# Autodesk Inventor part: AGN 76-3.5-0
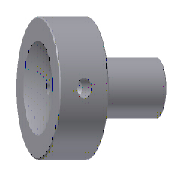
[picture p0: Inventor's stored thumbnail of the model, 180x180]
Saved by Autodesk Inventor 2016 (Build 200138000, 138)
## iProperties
IsCustomPart: 1
Created: 2015-02
Part Number: AGN 76-3.5-0
Material: DIN 1.2312
Description: Sprue Bushing
Document SubType Name: Modeling
Designer: Sandeep
Standard Revision: 1
Manufacturer: DME
Language: en-US
Size Designation: 76-3.5-0
Categories: <MemberInstance><Categories><Category DisplayName="Mold" InternalName="349578f2-f4d4-4954-8c09-8e99297a61c0" Mnemonic="MOLD"><Category DisplayName="Runners" Int
Density: 7.85 g/cm^3
Appearance: Default
Author: Sandeep
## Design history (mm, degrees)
sketch "Sketch1"
  geometry: L1 (0, -27.2)-(0, 23.2) reference; L2 (1.75, 20)-(19, 20); L3 (19, 20)-(19, 0); L4 (19, 0)-(12, 0); L5 (9, -3)-(9, -76); L6 (9, -76)-(4.264, -76); L7 (4.264, -76)-(1.75, 20); A1 r 3 centre (12, -3) between (12, 0) and (9, -3); 2 further points
  constraints: 12 end point, 3 parallel, 2 perpendicular, 2 point on circle, 2 point on line, 2 tangent, 1 centre point
  dimensions: "d0" = 18 diameter of L5 L1 (= D); "d3" = 38 diameter of L3 L1 (= d1); "d6" = 1.5 deg angle of L7 L1 (= 0.5 x Taper); "d7" = 20 distance between parallel lines of L4 L2 (= K_); "d8" = 76 distance between parallel lines of L4 L6 (= L); "d9" = 3 radius of A1 (= R3); "d62" = 3.5 diameter of point (1.75, 20) L1 (= d_); "d63" = 0 distance from line of point (1.75, 20) L2 (computed from Rd)
revolve "Revolution1" sketch "Sketch1" stored, may be unused: angle "d10" = 90 deg
sketch "Sketch2"
  geometry: L1 (0, -32.79)-(0, 56.739) reference; L2 (4.264, -76)-(1.75, 20) reference; L3 (-19, 20)-(19, 20) reference; L4 (0, 50.901)-(0, 19.901); A1 r 15.5 centre (0, 35.401) between (0, 19.901) and (0, 50.901); 2 further points
  constraints: 3 point on circle, 3 point on line, 2 end point, 1 centre point, 1 midpoint
  dimensions: "d64" = 0 distance from line of point (1.75, 20) L3 (computed from Rd); "d67" = 15.5 radius of A1 (= Rk)
revolve "Revolution2" sketch "Sketch2" stored, may be unused: angle "d13" = 90 deg
workplane "Work Plane1"
sketch "Sketch3"
  geometry: 2 further points
  constraints: 1 vertical alignment
  dimensions: "d43" = 10 distance of point (0, -10) point (0, 0) (= 0.5 x K_)
hole "Hole1" sketch "Sketch3" at (0, 0) diameter "d15" = 4 (= pd1); stored, may be unused: countersink angle "d19" = 90 deg, drill point angle "d21" = 118 deg; dims "d16" = 6, "d17" = 4, "d18" = 2, "d20" = 6 (= pl1)
chamfer "Chamfer1" distance "d22" = 0.3; stored, may be unused: second distance "d23" = 2, angle "d24" = 45 deg
sketch "Sketch4"
  geometry: L1 (0, -30.4)-(0, 42.4) reference; L2 (0, 40)-(19.5, 40); L3 (19.5, 40)-(19.5, 0); L4 (9, -76)-(0, -76); L5 (0, -76)-(0, 40); L6 (9, -3)-(9, -76); L7 (12, 0)-(19.5, 0); L8 (12, 0)-(9, -3); 2 further points
  constraints: 14 end point, 4 point on line, 2 horizontal, 2 parallel, 1 perpendicular, 1 vertical
  dimensions: "d56" = 3 distance of L7.start point (9, 0) (= R3_CS); "d57" = 3 distance of L6.start point (9, 0) (= d56); "d58" = 39 diameter of L3 L1 (= d1_CS); "d59" = 40 distance between parallel lines of L7 L2 (= K_CS); "d60" = 18 diameter of L6 L1 (= D_CS); "d61" = 76 distance between parallel lines of L7 L4 (= L_CS)
feature "RevolutionSrf1" sketch "Sketch4" dims angle "d33" = 90 deg
feature "Sculpt1"
split "Split1"
body "Solid1"
body "Srf1"
feature "Surface1"
body "Srf2"
other parameters: "L" = 76 [user parameter; used in 1 equation term], "d1" = 38 [user parameter; used in 1 equation term], "d_" = 3.5 [user parameter; used in 1 equation term], "D" = 18 [user parameter; used in 1 equation term], "K_" = 20 [user parameter; used in 2 equation terms], "R" = 0 [user parameter], "Taper" = 3 deg [user parameter; used in 1 equation term], "Rd" = 0 [user parameter; used in 2 equation terms], "R3" = 3 [user parameter; used in 1 equation term], "pd1" = 4 [user parameter; used in 1 equation term], "d1_CS" = 39 [user parameter; used in 1 equation term], "K_CS" = 40 [user parameter; used in 1 equation term], "d44" = 0, "d45" = 0, "d46" = 0, "L_CS" = 76 [user parameter; used in 1 equation term], "D_CS" = 18 [user parameter; used in 1 equation term], "pl1" = 6 [user parameter; used in 1 equation term], "R3_CS" = 3 [user parameter; used in 1 equation term], "Rk" = 15.5 [user parameter; used in 1 equation term]
